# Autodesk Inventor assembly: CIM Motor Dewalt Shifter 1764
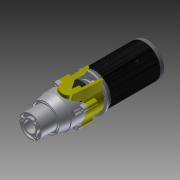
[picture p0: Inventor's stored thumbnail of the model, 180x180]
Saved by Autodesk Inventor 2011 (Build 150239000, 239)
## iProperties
Created: 2008-11
Part Number: CIM Motor Dewalt Shifter 1764
Document SubType Name: Assembly
Designer: lwoods
Author: lwoods
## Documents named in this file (11)
- R:\CAD Archives\Motors\CIM Motor Dewalt Shifter 1764\CIM Motor Dewalt Shifter 1764.iam
- R:\CAD Archives\Motors\CIM Motor Dewalt Shifter 1764\CIM Motor 1764.ipt
- R:\CAD Archives\Motors\CIM Motor Dewalt Shifter 1764\Chiaphua Plate 1764.ipt
- R:\CAD Archives\Motors\CIM Motor Dewalt Shifter 1764\Transmission Gear 1764.ipt
- R:\CAD Archives\Motors\CIM Motor Dewalt Shifter 1764\Transmission Top-Hat 1764.ipt
- R:\CAD Archives\Motors\CIM Motor Dewalt Shifter 1764\Switch 1764.ipt
- R:\CAD Archives\Motors\CIM Motor Dewalt Shifter 1764\Cut Drill Handle 1764.ipt
- R:\CAD Archives\Motors\CIM Motor Dewalt Shifter 1764\Cut Drill Handle Mirror 1764.ipt
- R:\CAD Archives\Motors\CIM Motor Dewalt Shifter 1764\Housing 1764.ipt
- R:\CAD Archives\Motors\CIM Motor Dewalt Shifter 1764\Mounting Cover 1764.ipt
- R:\CAD Archives\Motors\CIM Motor Dewalt Shifter 1764\Front Mounting Cover 1764.ipt
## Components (10 placed, 10 different names)
1. CIM Motor 1764:1 — Mate:2, Mate:3, Mate:27, Mate:28
2. Chiaphua Plate 1764:1 — Mate:2, Mate:3, Mate:17, Mate:18, Mate:19, Mate:27, Mate:29
3. Transmission Gear 1764:1 — Mate:4, Mate:5, Mate:6, Mate:14
4. Transmission Top-Hat 1764:1 — Mate:4, Mate:5, Mate:6, Mate:28, Mate:29
5. Cut Drill Handle 1764:1 — Flush:2, Mate:15, Mate:16, Mate:18, Mate:19, Mate:21, Angle:1, Mate:25
6. Cut Drill Handle Mirror 1764:1 — Flush:2, Mate:15, Mate:16, Mate:17, Mate:20
7. Housing 1764:1 — Mate:20, Mate:21, Angle:1, Mate:22, Mate:23, Mate:26
8. Mounting Cover 1764:1 — Mate:24, Angle:2, Flush:3
9. Front Mounting Cover 1764:1 — Mate:22, Mate:23, Mate:24, Angle:2, Flush:3
10. Switch 1764:1 — Mate:25, Mate:26
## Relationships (25: Mate 21, Flush 2, Angle 2)
- Mate:2: CIM Motor 1764:1 ↔ Chiaphua Plate 1764:1
- Mate:3: CIM Motor 1764:1 ↔ Chiaphua Plate 1764:1
- Mate:4: Transmission Gear 1764:1 ↔ Transmission Top-Hat 1764:1
- Mate:5: Transmission Gear 1764:1 ↔ Transmission Top-Hat 1764:1
- Mate:6: Transmission Gear 1764:1 ↔ Transmission Top-Hat 1764:1
- Mate:14: Transmission Gear 1764:1
- Flush:2: Cut Drill Handle 1764:1 ↔ Cut Drill Handle Mirror 1764:1
- Mate:15: Cut Drill Handle 1764:1 ↔ Cut Drill Handle Mirror 1764:1
- Mate:16: Cut Drill Handle 1764:1 ↔ Cut Drill Handle Mirror 1764:1
- Mate:17: Chiaphua Plate 1764:1 ↔ Cut Drill Handle Mirror 1764:1
- Mate:18: Chiaphua Plate 1764:1 ↔ Cut Drill Handle 1764:1
- Mate:19: Chiaphua Plate 1764:1 ↔ Cut Drill Handle 1764:1
- Mate:20: Cut Drill Handle Mirror 1764:1 ↔ Housing 1764:1
- Mate:21: Cut Drill Handle 1764:1 ↔ Housing 1764:1
- Angle:1: Cut Drill Handle 1764:1 ↔ Housing 1764:1
- Mate:22: Housing 1764:1 ↔ Front Mounting Cover 1764:1
- Mate:23: Housing 1764:1 ↔ Front Mounting Cover 1764:1
- Mate:24: Mounting Cover 1764:1 ↔ Front Mounting Cover 1764:1
- Angle:2: Mounting Cover 1764:1 ↔ Front Mounting Cover 1764:1
- Flush:3: Mounting Cover 1764:1 ↔ Front Mounting Cover 1764:1
- Mate:25: Cut Drill Handle 1764:1 ↔ Switch 1764:1
- Mate:26: Housing 1764:1 ↔ Switch 1764:1
- Mate:27: CIM Motor 1764:1 ↔ Chiaphua Plate 1764:1
- Mate:28: CIM Motor 1764:1 ↔ Transmission Top-Hat 1764:1
- Mate:29: Chiaphua Plate 1764:1 ↔ Transmission Top-Hat 1764:1
